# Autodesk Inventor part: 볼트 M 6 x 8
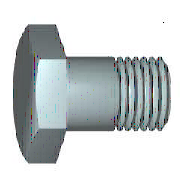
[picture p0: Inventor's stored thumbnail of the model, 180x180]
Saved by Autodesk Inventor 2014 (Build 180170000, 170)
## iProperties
Created: 2012-02
Part Number: 볼트 M 6 x 8
Material: 강철, 연강
Description: 6각 머리 볼트 및 6각 머리 나사
Document SubType Name: Modeling
Standard: KS B 1002
Designer: mduedu
Standards Organization: KS
Language: ko-KR
Size Designation: C  M 6 x 12
Categories: <MemberInstance><Categories><Category DisplayName="조임쇠" InternalName="e4da775c-781d-43d5-af7c-5136215cf5a6" Mnemonic="FSTN"><Category DisplayName="볼트" InternalN
Density: 7.86 g/cm^3
Mass: 4.46616 g
Surface Area: 4.51243 cm^2
Volume: 0.568214 cm^3
Appearance: 강철
IsCustomPart: 1
Author: mduedu
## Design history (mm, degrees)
sketch "스케치1"
  geometry: L1 (0, 3)-(8, 3); L2 (8, 3)-(8, 0); L3 (8, 0)-(0, 0); L4 (-2.4, 0)-(14.4, 0) reference; L5 (0, -0.6)-(0, 3.6) reference; L6 (0, 3)-(0, 0)
  constraints: 8 end point, 3 point on line, 1 collinear
  dimensions: "d2" = 6 diameter of L1 L3 (= GD); "d59" = 8 distance between parallel lines of L2 L5 (= NLG)
revolve "본체" sketch "스케치1" stored, may be unused: angle "d12" = 90 deg
sketch "스케치2"
  geometry: L1 (0, 5.774)-(5, 2.887); L2 (5, 2.887)-(5, -2.887); L3 (5, -2.887)-(0, -5.774); L4 (0, -5.774)-(-5, -2.887); L5 (-5, -2.887)-(-5, 2.887); L6 (-5, 2.887)-(0, 5.774); L7 (-7, 0)-(7, 0) reference; L8 (0, 8.083)-(0, -8.083) reference; 2 further points
  constraints: 12 end point, 2 midpoint, 1 coincident, 1 vertical, 11 other
  dimensions: "d11" = 10 distance between parallel lines of L5 L2 (= SW)
extrude "머리" join sketch "스케치2" distance "d3" = 4 (= KOH); taper "d4" = 0 deg
revolve "모따기1" stored, may be unused: angle "d21" = 90 deg
workplane "Work Plane1"
body "Solid1"
feature "스레드" dims "d15" = 9 (= GEL), "d16" = 0
chamfer "모따기2" distance "d6" = 0.61345 (= -0.5 x SPD + 0.5 x GD); stored, may be unused: second distance "d7" = 0.61355 (computed from GUL), angle "d55" = 45 deg
sketch "스케치4"
  geometry: L1 (-3.423, 6)-(-4, 5); L2 (-1.1, 0)-(-0.234, 0); L3 (-4.753, 0)-(0.519, 0) reference; L4 (-4, 6)-(-3.423, 6); L5 (-4, 5)-(-4, 6); L6 (0, 7.2)-(0, -1.2) reference
  constraints: 8 end point, 1 parallel, 1 perpendicular, 1 point on line
  dimensions: "d65" = 10 diameter of L1.end L2 (= SW); "d67" = 30 deg angle of L1 L5 (= ANG1); "d68" = 12 diameter of L4 L2 (= 1.2 x SW); "d69" = 4 distance between parallel lines of L5 L6 (= KOH)
other parameters: "NLG" = 8 [user parameter; used in 1 equation term], "GD" = 6 (= NND) [user parameter; used in 2 equation terms], "BDM" = 6 (= NND) [user parameter], "KOH" = 4 [user parameter; used in 2 equation terms], "GEL" = 9 [user parameter; used in 1 equation term], "SW" = 10 [user parameter; used in 5 equation terms], "SPD" = 4.7731 (= NND - 1.2269 x PTC) [user parameter; used in 1 equation term], "SD2" = 6 (= NND) [user parameter], "SD" = 0 [user parameter], "ANG1" = 30 deg [user parameter; used in 1 equation term], "GAL" = 0.61345 (= 0.61345 x PTC) [user parameter], "GUL" = 0.61345 (= 0.61345 x PTC) [user parameter; used in 1 equation term], "d8" = 0, "RR" = 0.25 [user parameter], "d58" = 0, "RR1" = 0.1 [user parameter], "GD1" = 4.7731 (= THREADDIA - 1.2269 x PTC) [user parameter], "THREADDIA" = 6 [user parameter; used in 1 equation term], "TOA" = 30 deg [user parameter], "PTC" = 1 [user parameter; used in 5 equation terms], "NND" = 6 [user parameter; used in 4 equation terms], "E0" = 11.55 (= 1.155 x SW) [user parameter]
